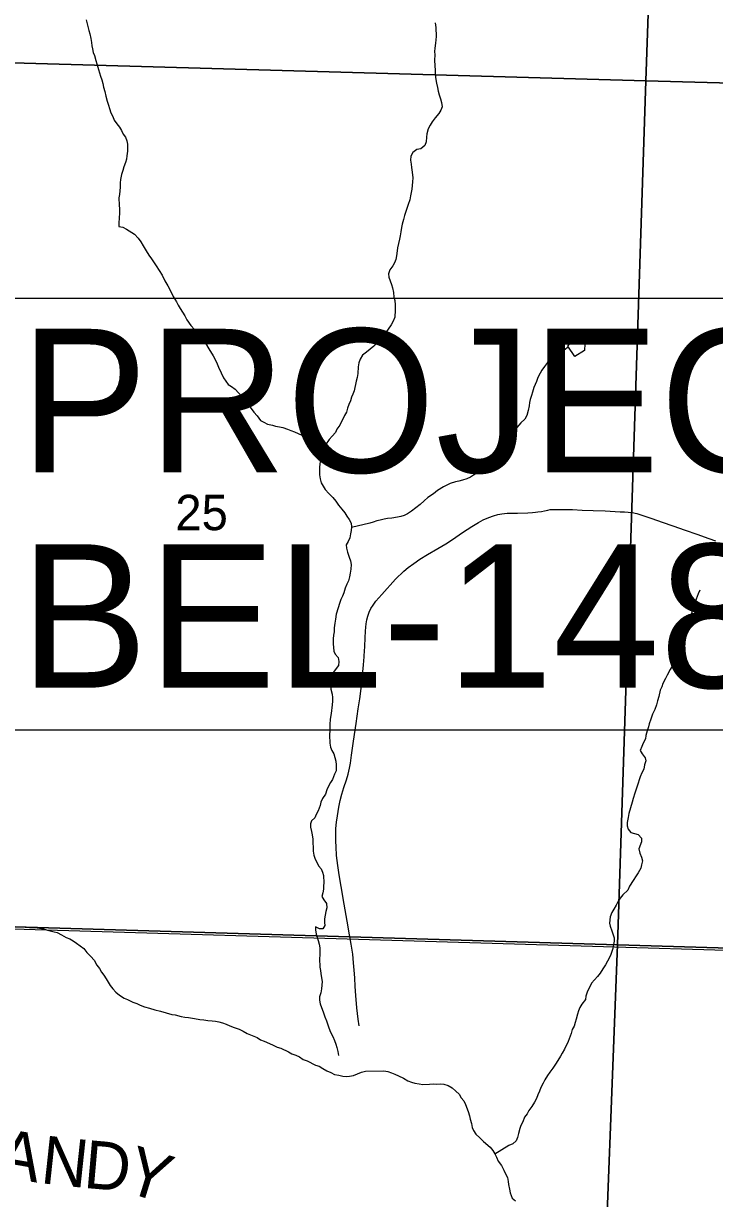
# Model space of a CAD drawing. Extents: x -7.9 to 76.1, y 0 to 22.
# Drawn here: x 6.604 to 7.423, y 17.882 to 19.274 of the extents above; entities that cross this region are included whole.
import ezdxf

# ---------------------------------------------------------------- set-up
doc = ezdxf.new("R2010")
doc.units = 0
for name, color, linetype in [('DV_X_Township_Line', 7, 'Continuous'), ('GM_X_Minor_River', 7, 'Continuous'), ('GM_X_Section', 7, 'Continuous'), ('GM_X_Section_Text', 7, 'Continuous'), ('GM_X_Township_Road', 7, 'Continuous'), ('GM_X_Township_Road_Text', 7, 'Continuous'), ('SH_Text', 7, 'Continuous')]:
    doc.layers.add(name, color=color, linetype=linetype)

msp = doc.modelspace()

# ---------------------------------------------------------------- linework, layer by layer
at = {"layer": 'DV_X_Township_Line'}
msp.add_lwpolyline([(5.4916, 20.9), (5.4589, 19.5934), (5.4537, 19.3537), (5.4527, 19.3121), (5.4518, 19.2705), (5.4514, 19.2515), (5.451, 19.2324), (5.4237, 18.2356), (6.0503, 18.2178), (7.6352, 18.1705), (8.1733, 18.1556), (8.2754, 18.1527), (8.3264, 18.1514), (8.3292, 18.1513), (8.3352, 18.1512), (8.3434, 18.151), (8.9, 18.1366), (8.9, 18.1366)], dxfattribs=at)
at = {"layer": 'GM_X_Minor_River'}
for points in [[(6.6787, 19.2779), (6.6803, 19.2714), (6.6819, 19.2654), (6.6831, 19.2612), (6.6843, 19.2559), (6.6851, 19.251), (6.6855, 19.2472), (6.6863, 19.2434), (6.6872, 19.2393), (6.6884, 19.2355), (6.6903, 19.2298), (6.6915, 19.2257), (6.6935, 19.2192), (6.6947, 19.2151), (6.6959, 19.2113), (6.6971, 19.2068), (6.6983, 19.2026), (6.6991, 19.1981), (6.7007, 19.1931), (6.7019, 19.1875), (6.7035, 19.1814), (6.7051, 19.1769), (6.7063, 19.1727), (6.7078, 19.1678), (6.7102, 19.1633), (6.7121, 19.1592), (6.7152, 19.1546), (6.7183, 19.1509), (6.7206, 19.1467), (6.7226, 19.1426), (6.7253, 19.1388), (6.7269, 19.1347), (6.7277, 19.1305), (6.7278, 19.1222), (6.7271, 19.1169), (6.7264, 19.113), (6.7253, 19.1089), (6.7235, 19.1039), (6.722, 19.0993), (6.7206, 19.0948), (6.7195, 19.0887), (6.7192, 19.0849), (6.7189, 19.0796), (6.7182, 19.0712), (6.7175, 19.067), (6.7177, 19.0583), (6.7181, 19.0541), (6.7181, 19.0499), (6.7179, 19.0427), (6.7176, 19.0378), (6.7176, 19.0332), (6.7222, 19.0322), (6.7264, 19.0299), (6.7359, 19.024), (6.7402, 19.0195), (6.7436, 19.015), (6.7464, 19.0101), (6.7499, 19.0045), (6.753, 18.9992), (6.7561, 18.9947), (6.7615, 18.9864), (6.7653, 18.9811), (6.7688, 18.9755), (6.772, 18.9687), (6.7754, 18.9631), (6.7786, 18.957), (6.7817, 18.9502), (6.7856, 18.9438), (6.7879, 18.9401), (6.7902, 18.9359), (6.7929, 18.9318), (6.7956, 18.9273), (6.798, 18.9228), (6.8026, 18.916), (6.8072, 18.9111), (6.8123, 18.9047), (6.8165, 18.9006), (6.82, 18.895), (6.8242, 18.8882), (6.8293, 18.8799), (6.8332, 18.8724), (6.8355, 18.8667), (6.8386, 18.8599), (6.8414, 18.8539), (6.8441, 18.8501), (6.8472, 18.846), (6.851, 18.8438), (6.8552, 18.8404), (6.8667, 18.8281), (6.8698, 18.8243), (6.8729, 18.8194), (6.8776, 18.8134), (6.8814, 18.8089), (6.8853, 18.8036), (6.8891, 18.8014), (6.8937, 18.7992)], [(7.0924, 19.2744), (7.0933, 19.2687)], [(7.0933, 19.2687), (7.0934, 19.2581), (7.0927, 19.2501), (7.0921, 19.2444), (7.0917, 19.2402), (7.0918, 19.2364), (7.0915, 19.23), (7.092, 19.2235), (7.0924, 19.2182), (7.0925, 19.2141), (7.0929, 19.2095), (7.0938, 19.2027), (7.095, 19.1978), (7.0958, 19.1936), (7.097, 19.1891), (7.0986, 19.1845), (7.0998, 19.18), (7.1006, 19.1747), (7.0991, 19.1709), (7.0965, 19.1671), (7.0924, 19.1617), (7.0887, 19.1571), (7.0865, 19.1533), (7.0839, 19.149), (7.0824, 19.143), (7.0821, 19.1388), (7.0818, 19.1335), (7.08, 19.1289), (7.0755, 19.125), (7.0706, 19.1242), (7.0657, 19.1207), (7.0635, 19.1165), (7.0631, 19.1119), (7.064, 19.107), (7.0644, 19.1029), (7.0652, 19.0976), (7.0657, 19.0907), (7.0654, 19.0862), (7.0651, 19.0816), (7.0647, 19.0774), (7.064, 19.0733), (7.0633, 19.0694), (7.0623, 19.0649), (7.0604, 19.0592), (7.0586, 19.0546), (7.0575, 19.0508), (7.0561, 19.0462), (7.055, 19.0413), (7.0532, 19.0359), (7.0525, 19.0321), (7.0518, 19.0268), (7.0507, 19.0222), (7.05, 19.018), (7.0489, 19.0131), (7.0478, 19.0081), (7.0475, 19.0043), (7.0465, 18.9986), (7.0458, 18.9941), (7.0443, 18.9903), (7.0421, 18.9864), (7.0387, 18.9818), (7.0369, 18.9772), (7.0373, 18.9731), (7.0389, 18.9689), (7.0405, 18.9644), (7.0417, 18.9606), (7.0429, 18.9549), (7.0433, 18.9493), (7.0445, 18.9455), (7.045, 18.9405), (7.0451, 18.9341), (7.0444, 18.9257), (7.0426, 18.9212), (7.04, 18.9166), (7.034, 18.9078), (7.0311, 18.9035), (7.0281, 18.8997), (7.0243, 18.8959), (7.0195, 18.8916), (7.0153, 18.8878), (7.0108, 18.8843), (7.0063, 18.8808), (7.0034, 18.8762), (7.0019, 18.8716), (7.0012, 18.8671), (7.0006, 18.8591), (6.9999, 18.8545), (6.9988, 18.85), (6.9963, 18.8385), (6.9948, 18.8347), (6.993, 18.8309), (6.9919, 18.8267), (6.9901, 18.8225), (6.9886, 18.8179), (6.9872, 18.8134), (6.9849, 18.8095), (6.9794, 18.7981), (6.9757, 18.7931), (6.9742, 18.7893), (6.9701, 18.7851), (6.9667, 18.7808)], [(7.2497, 18.8916), (7.2608, 18.9059), (7.2697, 18.8943), (7.2694, 18.8863), (7.2578, 18.8793), (7.2497, 18.8916)], [(7.2503, 18.8907), (7.2399, 18.8829), (7.235, 18.879), (7.2305, 18.8759), (7.2256, 18.872), (7.2219, 18.8674), (7.2189, 18.8632), (7.2168, 18.8596), (7.2141, 18.8544), (7.2123, 18.8495), (7.2093, 18.8426), (7.2075, 18.8369), (7.2064, 18.8331), (7.205, 18.8285), (7.2043, 18.8247), (7.2036, 18.8209), (7.2025, 18.8152), (7.2011, 18.8095), (7.1985, 18.8052), (7.194, 18.8006), (7.1891, 18.7953), (7.1846, 18.7918), (7.179, 18.786), (7.1738, 18.7799), (7.1678, 18.7733), (7.1633, 18.768), (7.1589, 18.7622), (7.154, 18.7561), (7.1466, 18.7465), (7.1428, 18.7419), (7.1379, 18.7388), (7.1342, 18.7364), (7.1297, 18.7345), (7.1247, 18.7329), (7.1202, 18.7317), (7.1164, 18.7309), (7.11, 18.7289), (7.1021, 18.725), (7.0953, 18.7207), (7.0905, 18.7165), (7.0837, 18.7122), (7.0792, 18.7084), (7.0747, 18.7041), (7.0695, 18.7002), (7.0642, 18.696), (7.0597, 18.6929), (7.0555, 18.691), (7.0518, 18.6898), (7.0476, 18.6889), (7.0408, 18.6877), (7.0359, 18.6873), (7.0317, 18.6868), (7.0272, 18.6856), (7.0234, 18.6848), (7.0189, 18.6832), (7.0151, 18.6817), (6.9931, 18.6766)], [(6.8937, 18.7992), (6.8994, 18.7978), (6.9032, 18.7967), (6.9078, 18.796), (6.9119, 18.7953), (6.9173, 18.7931), (6.9211, 18.7916), (6.9257, 18.7901), (6.9299, 18.7879), (6.9344, 18.7861), (6.9386, 18.7842), (6.9428, 18.7832), (6.9474, 18.7825), (6.955, 18.7769), (6.9595, 18.7677)], [(6.9667, 18.7808), (6.9623, 18.7747), (6.9601, 18.7701), (6.959, 18.7655), (6.9575, 18.7617), (6.9564, 18.7568), (6.9557, 18.7522), (6.9554, 18.748), (6.9551, 18.7431), (6.9552, 18.7393), (6.956, 18.7344), (6.9572, 18.7298), (6.9619, 18.7216), (6.9665, 18.7171), (6.9711, 18.7122), (6.9745, 18.7081), (6.9776, 18.7032), (6.9819, 18.6983), (6.9854, 18.6942), (6.9877, 18.69), (6.9904, 18.6863), (6.9927, 18.6817), (6.9932, 18.6776), (6.9928, 18.6734), (6.9921, 18.6692), (6.9911, 18.6646), (6.9892, 18.6601), (6.987, 18.6562), (6.9871, 18.6524), (6.9883, 18.6475), (6.9906, 18.6415), (6.9918, 18.6373), (6.9926, 18.6328), (6.9923, 18.6275), (6.9916, 18.6225), (6.9909, 18.6183), (6.9895, 18.6138), (6.9876, 18.6096), (6.9858, 18.605), (6.984, 18.5993), (6.9825, 18.5954), (6.9807, 18.5916), (6.9792, 18.5878), (6.9752, 18.5741), (6.9742, 18.5684), (6.9735, 18.5634), (6.9728, 18.5581), (6.9725, 18.5532), (6.9718, 18.5494), (6.9715, 18.5448), (6.9715, 18.5391), (6.9724, 18.5304), (6.974, 18.5266), (6.9774, 18.5229), (6.9783, 18.5179), (6.9776, 18.5134), (6.9727, 18.5065), (6.9697, 18.5026), (6.969, 18.4988), (6.9684, 18.4909), (6.9688, 18.4855), (6.9701, 18.4795), (6.9705, 18.4753), (6.9706, 18.4711), (6.9702, 18.4666), (6.9689, 18.4567), (6.9678, 18.4499), (6.9675, 18.4434), (6.9676, 18.4366), (6.9673, 18.4309), (6.9674, 18.4214), (6.9683, 18.4168), (6.9698, 18.4127), (6.9722, 18.4089), (6.9734, 18.4044), (6.9746, 18.4002), (6.975, 18.3957), (6.9751, 18.3888), (6.9732, 18.3846), (6.9707, 18.3785), (6.9681, 18.3747), (6.9659, 18.3705), (6.964, 18.3663), (6.9622, 18.3609), (6.9588, 18.356), (6.957, 18.3514), (6.9559, 18.3476), (6.9537, 18.3411), (6.9515, 18.3369), (6.9497, 18.333), (6.9459, 18.3296), (6.9445, 18.3258), (6.9445, 18.322), (6.9457, 18.3167), (6.9465, 18.3129), (6.9474, 18.3076), (6.9476, 18.2935), (6.9484, 18.2886), (6.95, 18.2841), (6.9519, 18.2803), (6.9542, 18.2762)], [(7.406, 18.6027), (7.4041, 18.5982), (7.3983, 18.5825), (7.3961, 18.5749), (7.3939, 18.568), (7.3918, 18.5604), (7.3907, 18.5562), (7.3892, 18.5509), (7.3882, 18.5459), (7.3867, 18.541), (7.3853, 18.5364), (7.3838, 18.5326), (7.382, 18.528), (7.3794, 18.5227), (7.3742, 18.5139), (7.3709, 18.5085), (7.3672, 18.502), (7.3653, 18.4978), (7.362, 18.4921), (7.3609, 18.4882), (7.3591, 18.484), (7.3573, 18.4768), (7.3558, 18.4715), (7.3547, 18.4669), (7.3525, 18.4612), (7.35, 18.4558), (7.3478, 18.4497), (7.3459, 18.4444), (7.3452, 18.4406), (7.3434, 18.436), (7.342, 18.4303), (7.3416, 18.4265), (7.339, 18.4215), (7.3372, 18.4173), (7.3354, 18.4127), (7.3377, 18.4086), (7.3412, 18.4041), (7.342, 18.4003), (7.3405, 18.3957), (7.3395, 18.3908), (7.3373, 18.3862), (7.3354, 18.3816), (7.334, 18.3778), (7.3329, 18.374), (7.3289, 18.3621), (7.327, 18.356), (7.326, 18.3515), (7.322, 18.3381), (7.3209, 18.3332), (7.3199, 18.3275), (7.3199, 18.3237), (7.3211, 18.3195), (7.3242, 18.3158), (7.3329, 18.3132), (7.3368, 18.3091), (7.3368, 18.3045), (7.3339, 18.2961), (7.3348, 18.2912), (7.3367, 18.2863), (7.3379, 18.2822), (7.3368, 18.2772), (7.3361, 18.2734), (7.3328, 18.268), (7.3306, 18.2642), (7.3272, 18.2589), (7.3228, 18.252), (7.3206, 18.2474), (7.3146, 18.242), (7.3116, 18.2378), (7.309, 18.2335), (7.3068, 18.2297), (7.3042, 18.2247), (7.3016, 18.2209), (7.2998, 18.2159), (7.2991, 18.2083), (7.2999, 18.2046), (7.3019, 18.1993), (7.3043, 18.1909), (7.3043, 18.1868), (7.3036, 18.183), (7.3029, 18.1784), (7.3018, 18.1746), (7.3, 18.17), (7.2967, 18.1631), (7.2941, 18.1589), (7.2911, 18.1543), (7.2878, 18.149), (7.2848, 18.1451), (7.2811, 18.1413), (7.2777, 18.1374), (7.2755, 18.1328), (7.2729, 18.1279), (7.2711, 18.1218), (7.2704, 18.118), (7.2663, 18.1122), (7.2637, 18.1084), (7.2622, 18.1046), (7.2611, 18.1004), (7.2593, 18.0946), (7.2582, 18.0908), (7.2572, 18.0863)], [(6.9542, 18.2762), (6.9573, 18.2724), (6.9589, 18.2686), (6.9601, 18.2648), (6.9602, 18.2561), (6.9599, 18.2523), (6.9599, 18.2485), (6.9592, 18.244), (6.9582, 18.2398), (6.9605, 18.236), (6.9636, 18.2315), (6.964, 18.2266), (6.9626, 18.222), (6.9619, 18.2178), (6.9612, 18.2132), (6.9612, 18.209), (6.9617, 18.2053), (6.9591, 18.2014), (6.9553, 18.2014), (6.9507, 18.204), (6.9504, 18.2002), (6.9512, 18.1952), (6.9536, 18.1877), (6.9548, 18.1835), (6.9556, 18.179), (6.9557, 18.1702), (6.9554, 18.1664), (6.9555, 18.1562), (6.9563, 18.1524), (6.9567, 18.1486), (6.9576, 18.1437), (6.9584, 18.1391), (6.9578, 18.1304), (6.9567, 18.1258), (6.9552, 18.1209), (6.9553, 18.1171), (6.9561, 18.1129), (6.9577, 18.1084), (6.9596, 18.1031), (6.9616, 18.0974), (6.9636, 18.0925), (6.9652, 18.088), (6.9663, 18.0842), (6.9683, 18.0793), (6.971, 18.074), (6.973, 18.0695), (6.9746, 18.0649), (6.9758, 18.0612), (6.977, 18.0562), (6.9778, 18.0517)], [(6.6014, 18.2038), (6.6117, 18.2031), (6.6174, 18.2032), (6.6235, 18.2022), (6.628, 18.2015), (6.633, 18.2), (6.6406, 18.1978), (6.6444, 18.1971), (6.6493, 18.1945), (6.6551, 18.1912), (6.6593, 18.1897), (6.6635, 18.1875), (6.6673, 18.1845), (6.6715, 18.1816), (6.6761, 18.1782), (6.6796, 18.1737), (6.6842, 18.1688), (6.6881, 18.1643), (6.6915, 18.1587), (6.6946, 18.1545), (6.697, 18.1504), (6.6997, 18.1466), (6.7024, 18.1425), (6.7047, 18.1383), (6.707, 18.1346), (6.7105, 18.1304), (6.714, 18.1267), (6.7182, 18.123), (6.7236, 18.1196), (6.7278, 18.1178), (6.7342, 18.1148), (6.7388, 18.113), (6.7426, 18.1111), (6.748, 18.1093), (6.7537, 18.1075), (6.7602, 18.1057), (6.767, 18.1039), (6.7803, 18.1003), (6.7841, 18.0996), (6.7914, 18.0977), (6.7955, 18.097), (6.8001, 18.0964), (6.8073, 18.0953), (6.8134, 18.0943), (6.8183, 18.0939), (6.8229, 18.0932), (6.8282, 18.0926), (6.832, 18.0922), (6.8358, 18.0915), (6.8404, 18.0904), (6.8446, 18.0886), (6.8491, 18.0868), (6.8541, 18.0849), (6.8602, 18.0827), (6.8648, 18.0805), (6.8694, 18.0775)], [(6.8694, 18.0775), (6.8736, 18.0761), (6.8812, 18.0728), (6.8854, 18.0702), (6.8896, 18.0687), (6.8961, 18.0658), (6.9003, 18.0639), (6.9049, 18.0613), (6.9094, 18.0602), (6.9186, 18.0558), (6.9224, 18.0536), (6.9274, 18.0518), (6.9316, 18.0499), (6.9358, 18.0469), (6.9407, 18.0451), (6.9506, 18.0403), (6.9548, 18.0388), (6.9594, 18.0362), (6.964, 18.0333), (6.9686, 18.0314), (6.9732, 18.0292), (6.9781, 18.0281), (6.9831, 18.0271), (6.9872, 18.0267), (6.991, 18.0272), (6.9956, 18.028), (7.0001, 18.03), (7.005, 18.0319), (7.0099, 18.0331), (7.0315, 18.0334), (7.0361, 18.0327), (7.0406, 18.0309), (7.0445, 18.0294), (7.049, 18.0276), (7.0548, 18.0246), (7.0601, 18.0217), (7.0643, 18.0198), (7.0681, 18.0187), (7.0734, 18.018), (7.0776, 18.0173), (7.0856, 18.0175), (7.0901, 18.0179), (7.0939, 18.0176), (7.0988, 18.018), (7.1026, 18.0177), (7.1076, 18.0159), (7.1126, 18.0133), (7.1168, 18.0095), (7.1206, 18.0058), (7.1233, 18.0016), (7.1264, 17.9979), (7.1284, 17.9937), (7.1315, 17.9854), (7.1331, 17.9801), (7.1339, 17.976), (7.1355, 17.971), (7.1363, 17.9665), (7.1379, 17.9627), (7.1406, 17.9586), (7.1452, 17.9541), (7.1498, 17.9496), (7.1575, 17.9429), (7.1606, 17.9391), (7.1629, 17.9353), (7.1652, 17.9312), (7.1672, 17.9263), (7.1711, 17.9214), (7.1738, 17.9157), (7.1758, 17.9116), (7.1781, 17.9071), (7.1789, 17.9025), (7.1793, 17.8987), (7.1806, 17.8934), (7.1814, 17.8889), (7.1837, 17.8828), (7.1876, 17.8795)], [(7.2572, 18.0863), (7.2549, 18.0824), (7.2535, 18.0775), (7.2498, 18.0683), (7.2458, 18.0591), (7.2428, 18.0545), (7.241, 18.0507), (7.2358, 18.0423), (7.2317, 18.0365), (7.2283, 18.0319), (7.2254, 18.0277), (7.2224, 18.0227), (7.2202, 18.0189), (7.2176, 18.0136), (7.2161, 18.0094), (7.2139, 18.0048), (7.2125, 18.0006), (7.2102, 17.9964), (7.2069, 17.991), (7.2035, 17.9864), (7.2013, 17.9826), (7.1984, 17.9784), (7.1961, 17.973), (7.1939, 17.9688), (7.1925, 17.965), (7.191, 17.9593), (7.19, 17.9543), (7.1885, 17.9505), (7.1844, 17.947), (7.1798, 17.9451), (7.1632, 17.9349)]]:
    msp.add_lwpolyline(points, dxfattribs=at)
at = {"layer": 'GM_X_Section'}
for points in [[(6.3589, 20.2537), (7.3774, 20.223), (7.3421, 19.2056), (6.3267, 19.2345)], [(7.3774, 20.223), (8.3939, 20.1994), (8.3601, 19.1779), (7.3421, 19.2056)], [(6.3267, 19.2345), (7.3421, 19.2056), (7.3083, 18.1826), (6.2899, 18.213)], [(7.3421, 19.2056), (8.3601, 19.1779), (8.3283, 18.1522), (7.3083, 18.1826)], [(7.3083, 18.1826), (7.2713, 17.2194), (6.2529, 17.2478), (6.2899, 18.213)], [(7.3083, 18.1826), (8.3283, 18.1522), (8.2894, 17.1874), (7.2713, 17.2194)]]:
    msp.add_lwpolyline(points, close=True, dxfattribs=at)
at = {"layer": 'GM_X_Township_Road'}
for points in [[(6.9909, 18.1945), (6.9882, 18.2108), (6.9846, 18.2306), (6.9809, 18.2517), (6.9784, 18.2654), (6.9768, 18.2765), (6.9755, 18.2885), (6.9749, 18.2986), (6.9747, 18.3052), (6.9748, 18.3204), (6.9754, 18.3277), (6.9764, 18.3353), (6.978, 18.3457), (6.9797, 18.3536), (6.9816, 18.3609), (6.984, 18.3688), (6.9871, 18.3781), (6.9892, 18.3848), (6.9908, 18.3917), (6.9921, 18.3979), (6.9931, 18.4071), (6.9954, 18.4237), (6.9988, 18.4448), (7.0011, 18.462), (7.003, 18.474), (7.0048, 18.4863), (7.0058, 18.4958), (7.0066, 18.5058), (7.0074, 18.5143), (7.008, 18.5236), (7.0081, 18.5248), (7.009, 18.5358), (7.0095, 18.5462), (7.0097, 18.5542), (7.01, 18.5587), (7.0106, 18.5628), (7.0115, 18.5674), (7.0126, 18.5716), (7.0142, 18.5766), (7.0162, 18.5807), (7.0187, 18.5848), (7.0222, 18.5894), (7.029, 18.5974), (7.0455, 18.6154), (7.0552, 18.6249), (7.0604, 18.6293), (7.0669, 18.6341), (7.0742, 18.6391), (7.0833, 18.6448), (7.0955, 18.6517), (7.1048, 18.6576), (7.1127, 18.6627), (7.1249, 18.671), (7.1356, 18.678), (7.1437, 18.6828), (7.1492, 18.6857), (7.1559, 18.6885), (7.1616, 18.6906), (7.1667, 18.692), (7.1713, 18.6929), (7.1776, 18.6936), (7.1833, 18.6938), (7.19, 18.6939), (7.202, 18.694), (7.2078, 18.6945), (7.2111, 18.6948)], [(7.2111, 18.6948), (7.2141, 18.6952), (7.2184, 18.6958), (7.2219, 18.6965), (7.2257, 18.6973), (7.2287, 18.6979), (7.2333, 18.6982), (7.2433, 18.6981), (7.2551, 18.6979), (7.2664, 18.6974), (7.2794, 18.6969), (7.2939, 18.6963), (7.3114, 18.6955), (7.3167, 18.6953), (7.3211, 18.6949), (7.3257, 18.6944), (7.3313, 18.6933), (7.3386, 18.691), (7.3492, 18.6874), (7.3613, 18.6832), (7.374, 18.6788), (7.3886, 18.6737), (7.4024, 18.6689), (7.4167, 18.6639), (7.4245, 18.6609)], [(7.0024, 18.0867), (7.0012, 18.0945), (6.9997, 18.108), (6.9982, 18.1226), (6.9976, 18.1334), (6.997, 18.1436), (6.9964, 18.1526), (6.9957, 18.1611), (6.9946, 18.1714), (6.9927, 18.1834), (6.9909, 18.1945)]]:
    msp.add_lwpolyline(points, dxfattribs=at)
at = {"layer": 'SH_Text'}
msp.add_lwpolyline([(6.5481, 18.9482), (8.7892, 18.9482), (8.7892, 18.4369), (6.5481, 18.4369)], close=True, dxfattribs=at)

# ---------------------------------------------------------------- texts
at = {"layer": 'GM_X_Section_Text'}
msp.add_text('25', height=0.04186, rotation=0, dxfattribs=at).set_placement((6.7844, 18.6736))
at = {"layer": 'GM_X_Township_Road_Text'}
for s, rotation, p in [('A', 350.4064, (6.5706, 17.9094)), ('N', 353.8149, (6.6235, 17.9005)), ('D', 354.9771, (6.6745, 17.895)), ('Y', 342.8116, (6.7212, 17.8913))]:
    msp.add_text(s, height=0.0568, rotation=rotation, dxfattribs=at).set_placement(p)
at = {"layer": 'SH_Text'}
for s, p in [('PROJECT LOCATION', (6.6002, 18.742)), ('BEL-148-3.12', (6.6002, 18.487))]:
    msp.add_text(s, height=0.17, dxfattribs=at).set_placement(p)

doc.saveas('drawing.dxf')
